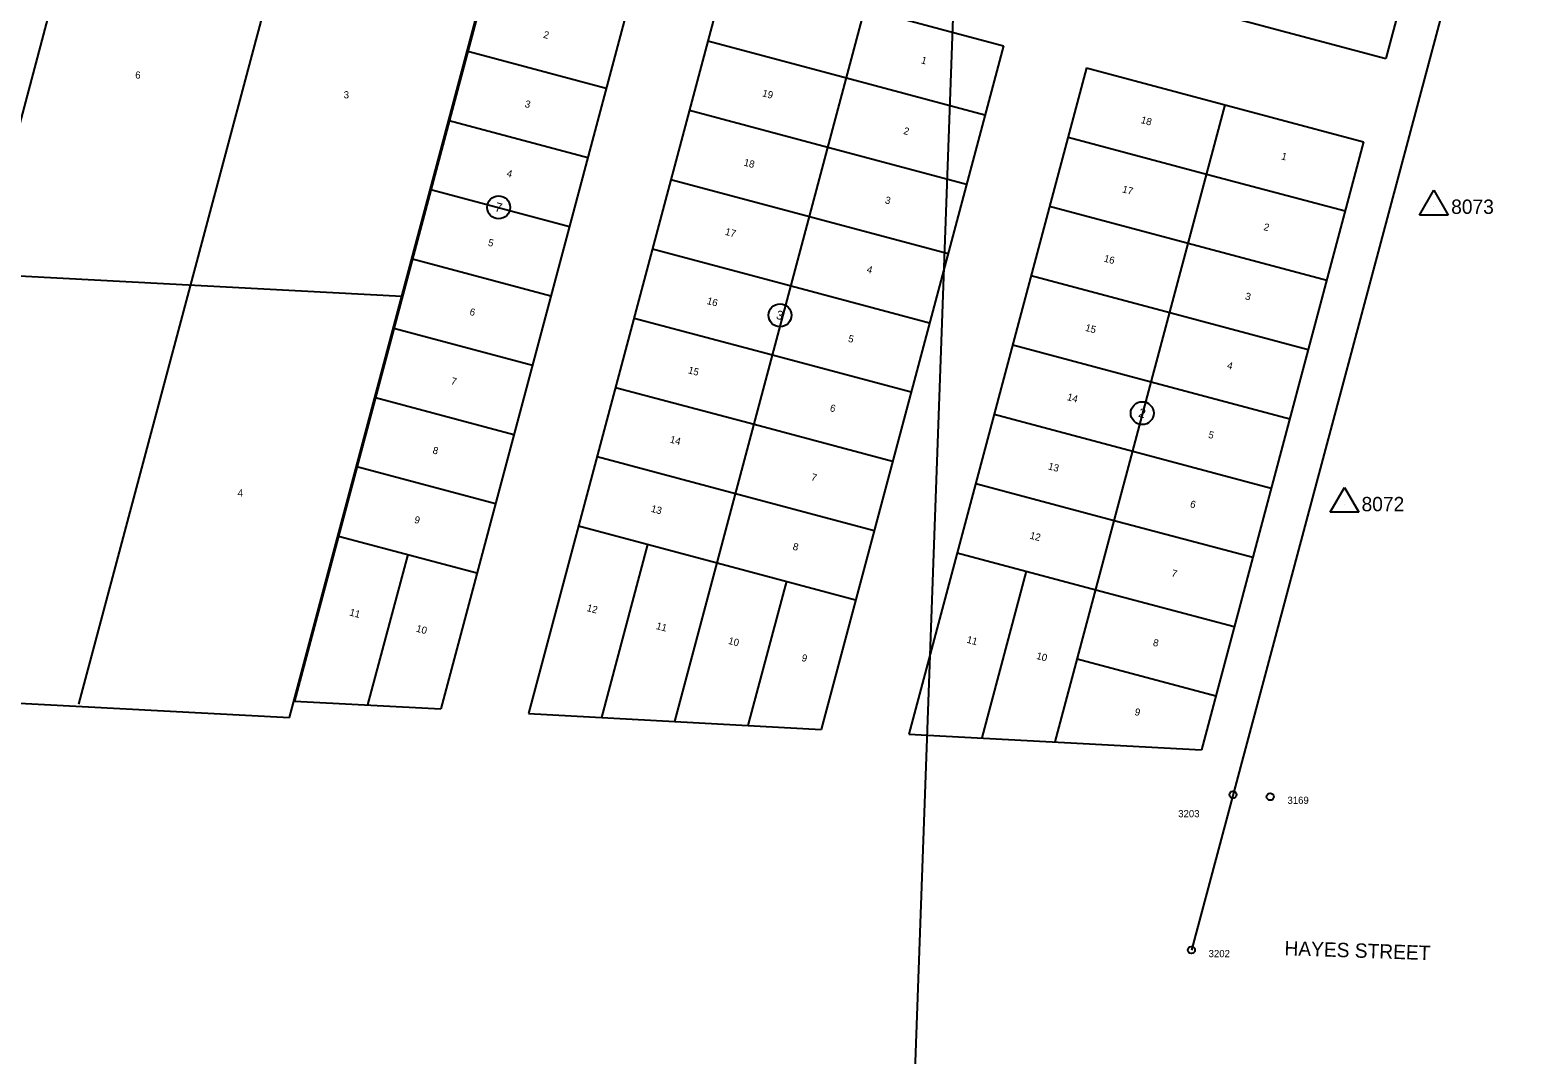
# Model space of a CAD drawing. Extents: x 7581380 to 7602708, y 543740 to 556109.
# Drawn here: x 7593146 to 7594197, y 548117 to 548831 of the extents above; entities that cross this region are included whole.
import ezdxf

# ---------------------------------------------------------------- set-up
doc = ezdxf.new("R2010")
doc.units = 0
for name, color, linetype in [('E_SURV_BNDRY_CROW', 7, 'Continuous'), ('E_SURV_BNDRY_GovSixSectLine', 7, 'Continuous'), ('E_SURV_BNDRY_Property', 7, 'Continuous'), ('E_SURV_BNDRY_SROW', 7, 'Continuous'), ('E_SURV_BNDRY_SubdivisionTx', 7, 'Continuous'), ('E_SURV_MON_FdMon', 7, 'Continuous'), ('E_SURV_MON_FdMonTx', 7, 'Continuous'), ('E_SURV_NTW_SetNtwPt', 7, 'Continuous'), ('E_SURV_NTW_SetNtwPtTx', 7, 'Continuous'), ('P_RW_ALIGN_Sec', 7, 'Continuous')]:
    doc.layers.add(name, color=color, linetype=linetype)

msp = doc.modelspace()

# ---------------------------------------------------------------- linework, layer by layer
at = {"layer": 'E_SURV_BNDRY_CROW'}
for p, q in [((7593631.5, 548872), (7593824.7, 548820.4)), ((7593824.7, 548820.4), (7593697.5, 548343.6)), ((7593882.7, 548805), (7593758.7, 548340.3)), ((7593882.7, 548805), (7594075.9, 548753.4))]:
    msp.add_line(p, q, dxfattribs=at)
at = {"layer": 'E_SURV_BNDRY_GovSixSectLine'}
msp.add_lwpolyline([(7593837.4, 550167.1), (7593741.9, 547525.5)], dxfattribs=at)
at = {"layer": 'E_SURV_BNDRY_Property'}
for p, q in [((7593032.7, 548369.1), (7593188.4, 548953)), ((7593179.9, 548361.2), (7593335.7, 548945.2)), ((7593326.7, 548351.8), (7593476.5, 548913.3)), ((7593476.9, 548913.2), (7593330.2, 548363.3)), ((7593573.5, 548887.5), (7593432.2, 548357.8)), ((7593631.5, 548872), (7593493.5, 548354.6)), ((7593898.2, 548863), (7594091.4, 548811.4)), ((7593595.5, 548349.1), (7593728.1, 548846.2)), ((7593618.6, 548823.7), (7593715.2, 548797.9)), ((7593451.1, 548816.6), (7593547.7, 548790.8)), ((7593715.2, 548797.9), (7593811.8, 548772.1)), ((7593605.7, 548775.4), (7593702.3, 548749.6)), ((7593860.8, 548334.8), (7593979.3, 548779.2)), ((7593438.2, 548768.3), (7593534.9, 548742.5)), ((7593702.3, 548749.6), (7593799, 548723.8)), ((7593869.8, 548756.7), (7593966.4, 548730.9)), ((7593966.4, 548730.9), (7594063.1, 548705.1)), ((7593425.3, 548720), (7593522, 548694.2)), ((7593592.8, 548727.1), (7593689.5, 548701.3)), ((7593856.9, 548708.4), (7593953.6, 548682.6)), ((7593689.5, 548701.3), (7593786.1, 548675.5)), ((7593579.9, 548678.8), (7593676.6, 548653)), ((7593953.6, 548682.6), (7594050.2, 548656.8)), ((7593412.5, 548671.7), (7593509.1, 548645.9)), ((7593844, 548660.1), (7593940.7, 548634.3)), ((7593676.6, 548653), (7593773.2, 548627.2)), ((7593940.7, 548634.3), (7594037.3, 548608.5)), ((7593399.6, 548623.4), (7593496.2, 548597.6)), ((7593567.1, 548630.4), (7593663.7, 548604.7)), ((7593663.7, 548604.7), (7593760.3, 548578.9)), ((7593831.2, 548611.7), (7593927.8, 548586)), ((7593554.2, 548582.1), (7593650.8, 548556.4)), ((7593927.8, 548586), (7594024.4, 548560.2)), ((7593386.7, 548575.1), (7593483.3, 548549.3)), ((7593818.3, 548563.4), (7593914.9, 548537.7)), ((7593650.8, 548556.4), (7593747.4, 548530.6)), ((7593541.3, 548533.8), (7593637.9, 548508)), ((7593914.9, 548537.7), (7594011.5, 548511.9)), ((7593373.8, 548526.8), (7593470.4, 548501)), ((7593637.9, 548508), (7593734.5, 548482.3)), ((7593805.4, 548515.1), (7593902, 548489.3)), ((7593902, 548489.3), (7593998.6, 548463.6)), ((7593360.9, 548478.4), (7593457.5, 548452.7)), ((7593528.4, 548485.5), (7593625, 548459.7)), ((7593409.2, 548465.6), (7593381.2, 548360.6)), ((7593544.5, 548351.8), (7593576.7, 548472.6)), ((7593792.5, 548466.8), (7593889.1, 548441)), ((7593625, 548459.7), (7593721.6, 548434)), ((7593673.3, 548446.9), (7593646.5, 548346.3)), ((7593809.8, 548337.6), (7593840.8, 548453.9)), ((7593889.1, 548441), (7593985.7, 548415.3)), ((7593876.2, 548392.7), (7593972.8, 548366.9)), ((7593330.2, 548363.3), (7593432.2, 548357.8)), ((7593493.5, 548354.6), (7593697.5, 548343.6)), ((7593758.7, 548340.3), (7593962.8, 548329.3))]:
    msp.add_line(p, q, dxfattribs=at)
for points in [[(7594173.9, 549120.6), (7594091.4, 548811.4)], [(7591427.6, 548750.7), (7593405.1, 548645.7)], [(7594075.9, 548753.4), (7593962.8, 548329.3)], [(7591415.8, 548453.2), (7593326.7, 548351.8)]]:
    msp.add_lwpolyline(points, dxfattribs=at)
at = {"layer": 'E_SURV_BNDRY_SubdivisionTx'}
for centre in [(7593472.6, 548707.6), (7593668.9, 548632.4), (7593921.5, 548564.1)]:
    msp.add_circle(centre, 8, dxfattribs=at)
at = {"layer": 'E_SURV_MON_FdMon'}
for centre in [(7593984.8, 548298), (7594010.8, 548296.6), (7593955.8, 548189.7)]:
    msp.add_circle(centre, 2.5, dxfattribs=at)
at = {"layer": 'E_SURV_NTW_SetNtwPt'}
for p, q in [((7594115, 548702.3), (7594125, 548719.6)), ((7594125, 548719.6), (7594135, 548702.3)), ((7594125, 548708.1), (7594125, 548708.1)), ((7594135, 548702.3), (7594115, 548702.3)), ((7594052.5, 548495), (7594062.5, 548512.3)), ((7594062.5, 548512.3), (7594072.5, 548495)), ((7594062.5, 548500.7), (7594062.5, 548500.7)), ((7594072.5, 548495), (7594052.5, 548495))]:
    msp.add_line(p, q, dxfattribs=at)
at = {"layer": 'P_RW_ALIGN_Sec'}
msp.add_line((7594323.4, 549564.6), (7593955.8, 548189.7), dxfattribs=at)

# ---------------------------------------------------------------- texts
at = {"layer": 'E_SURV_BNDRY_SROW'}
msp.add_text('HAYES STREET', height=10, rotation=358.043, dxfattribs=at).set_placement((7594020.6, 548186.1))
at = {"layer": 'E_SURV_BNDRY_SubdivisionTx'}
for s, height, rotation, p in [('2', 5, 345.0633, (7593503.4, 548826)), ('1', 5, 345.0633, (7593766.9, 548808.2)), ('6', 5, 358.4615, (7593219.1, 548797.5)), ('3', 5, 358.4615, (7593364.5, 548783.7)), ('3', 5, 345.0633, (7593490.5, 548777.7)), ('19', 5, 345.0633, (7593656.1, 548785.2)), ('18', 5, 345.0633, (7593920.2, 548766.5)), ('2', 5, 345.0633, (7593754.6, 548758.9)), ('18', 5, 345.0633, (7593643.2, 548736.9)), ('1', 5, 345.0633, (7594018.1, 548741.2)), ('4', 5, 345.0633, (7593477.8, 548729.3)), ('17', 5, 345.0633, (7593907.2, 548718.2)), ('7', 6.3, 345.0633, (7593469.6, 548705.2)), ('3', 5, 345.0633, (7593741.7, 548710.6)), ('2', 5, 345.0633, (7594005.8, 548691.9)), ('5', 5, 345.0633, (7593464.8, 548681)), ('17', 5, 345.0633, (7593630.2, 548688.6)), ('4', 5, 345.0633, (7593729, 548662.3)), ('16', 5, 345.0633, (7593894.4, 548669.9)), ('16', 5, 345.0633, (7593617.5, 548640.3)), ('3', 5, 345.0633, (7593992.9, 548643.6)), ('6', 5, 345.0633, (7593452, 548632.7)), ('3', 6.3, 345.0633, (7593665.7, 548630)), ('15', 5, 345.0633, (7593881.4, 548621.6)), ('5', 5, 345.0633, (7593716, 548614)), ('15', 5, 345.0633, (7593604.4, 548592)), ('4', 5, 345.0633, (7593980.3, 548595.3)), ('7', 5, 345.0633, (7593439, 548584.4)), ('6', 5, 345.0633, (7593703.3, 548565.6)), ('14', 5, 345.0633, (7593868.7, 548573.3)), ('2', 6.3, 345.0633, (7593918.4, 548561.7)), ('5', 5, 345.0633, (7593967.2, 548547)), ('8', 5, 345.0633, (7593426.2, 548536.1)), ('14', 5, 345.0633, (7593591.7, 548543.7)), ('13', 5, 345.0633, (7593855.5, 548525)), ('7', 5, 345.0633, (7593690.2, 548517.4)), ('4', 5, 358.4615, (7593290.5, 548506)), ('13', 5, 345.0633, (7593578.5, 548495.4)), ('6', 5, 345.0633, (7593954.5, 548498.6)), ('9', 5, 345.0633, (7593413.4, 548487.7)), ('12', 5, 345.0633, (7593842.7, 548476.7)), ('8', 5, 345.0633, (7593677.4, 548469)), ('7', 5, 345.0633, (7593941.5, 548450.4)), ('11', 5, 345.0633, (7593368.2, 548423.1)), ('12', 5, 345.0633, (7593533.7, 548426.2)), ('10', 5, 345.0633, (7593414.7, 548411.8)), ('11', 5, 345.0633, (7593582.1, 548413.6)), ('10', 5, 345.0633, (7593632.4, 548403.3)), ('11', 5, 345.0633, (7593798.7, 548404.1)), ('8', 5, 345.0633, (7593928.6, 548402)), ('9', 5, 345.0633, (7593683.5, 548391.4)), ('10', 5, 345.0633, (7593847.3, 548392.8)), ('9', 5, 345.0633, (7593915.8, 548353.7))]:
    msp.add_text(s, height=height, rotation=rotation, dxfattribs=at).set_placement(p)
at = {"layer": 'E_SURV_MON_FdMonTx'}
for s, p in [('3169', (7594022.8, 548291.6)), ('3203', (7593946.6, 548282.3)), ('3202', (7593967.8, 548184.7))]:
    msp.add_text(s, height=5, dxfattribs=at).set_placement(p)
at = {"layer": 'E_SURV_NTW_SetNtwPtTx'}
for s, p in [('8073', (7594137, 548703.1)), ('8072', (7594074.5, 548495.7))]:
    msp.add_text(s, height=10, dxfattribs=at).set_placement(p)

doc.saveas('drawing.dxf')
